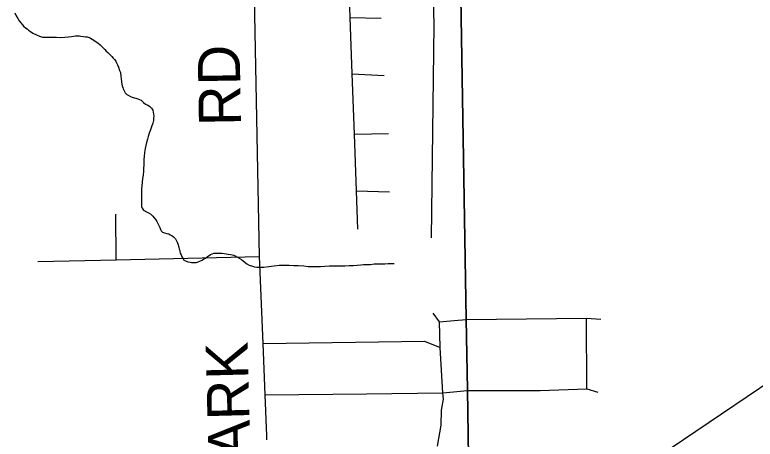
# Model space of a CAD drawing. Extents: x -59 to 82, y -3 to 49.
# Drawn here: x -51.187 to -50.187, y 46.792 to 47.366 of the extents above; entities that cross this region are included whole.
import ezdxf

# ---------------------------------------------------------------- set-up
doc = ezdxf.new("R2010")
doc.units = 0
for name, color, linetype in [('GM_X_Corporation', 7, 'Continuous'), ('GM_X_County_Road', 7, 'Continuous'), ('GM_X_County_Road_Text', 7, 'Continuous'), ('GM_X_Minor_River', 7, 'Continuous'), ('GM_X_Rail_Line', 7, 'Continuous'), ('GM_X_Township_Road', 7, 'Continuous')]:
    doc.layers.add(name, color=color, linetype=linetype)

msp = doc.modelspace()

# ---------------------------------------------------------------- linework, layer by layer
at = {"layer": 'GM_X_Corporation'}
for p, q in [((-50.5771, 46.9545), (-50.5847, 47.4155)), ((-50.5847, 47.4155), (-50.5771, 46.9545)), ((-50.5755, 46.8588), (-50.5771, 46.9545)), ((-50.5771, 46.9545), (-50.5755, 46.8588)), ((-50.5728, 46.6943), (-50.5755, 46.8588)), ((-50.5755, 46.8588), (-50.5728, 46.6943))]:
    msp.add_line(p, q, dxfattribs=at)
at = {"layer": 'GM_X_County_Road'}
for p, q in [((-50.8566, 47.039), (-50.8648, 47.4723)), ((-50.8518, 46.9215), (-50.8566, 47.039)), ((-50.8489, 46.8521), (-50.8518, 46.9215)), ((-50.8467, 46.7967), (-50.8489, 46.8521)), ((-50.8466, 46.7913), (-50.8467, 46.7967))]:
    msp.add_line(p, q, dxfattribs=at)
at = {"layer": 'GM_X_Minor_River'}
for p, q in [((-51.1872, 47.3684), (-51.1853, 47.3642)), ((-51.1853, 47.3642), (-51.183, 47.3605)), ((-51.183, 47.3605), (-51.1814, 47.3574)), ((-51.1814, 47.3574), (-51.1791, 47.3548)), ((-51.1791, 47.3548), (-51.1768, 47.3521)), ((-51.1768, 47.3521), (-51.1749, 47.3499)), ((-51.1749, 47.3499), (-51.173, 47.348)), ((-51.173, 47.348), (-51.1707, 47.3469)), ((-51.1707, 47.3469), (-51.1688, 47.345)), ((-51.1688, 47.345), (-51.1661, 47.3431)), ((-51.1661, 47.3431), (-51.1627, 47.3408)), ((-51.1627, 47.3408), (-51.1581, 47.3386)), ((-51.1581, 47.3386), (-51.1539, 47.3367)), ((-51.1539, 47.3367), (-51.1497, 47.3356)), ((-51.1106, 47.3363), (-51.108, 47.3367)), ((-51.108, 47.3367), (-51.105, 47.3371)), ((-51.105, 47.3371), (-51.1027, 47.3371)), ((-51.1027, 47.3371), (-51.1, 47.3371)), ((-51.1, 47.3371), (-51.0981, 47.3367)), ((-51.0981, 47.3367), (-51.0943, 47.3364)), ((-51.1497, 47.3356), (-51.1467, 47.3356)), ((-51.1467, 47.3356), (-51.1437, 47.3353)), ((-51.1437, 47.3353), (-51.1403, 47.3353)), ((-51.1403, 47.3353), (-51.1361, 47.3353)), ((-51.1361, 47.3353), (-51.1308, 47.3354)), ((-51.1308, 47.3354), (-51.1251, 47.335)), ((-51.1251, 47.335), (-51.1197, 47.3354)), ((-51.1197, 47.3354), (-51.1148, 47.3359)), ((-51.1148, 47.3359), (-51.1106, 47.3363)), ((-51.0943, 47.3364), (-51.0917, 47.336)), ((-51.0917, 47.336), (-51.0894, 47.3357)), ((-51.0894, 47.3357), (-51.0867, 47.3349)), ((-51.0867, 47.3349), (-51.0848, 47.3342)), ((-51.0848, 47.3342), (-51.0825, 47.3327)), ((-51.0825, 47.3327), (-51.0749, 47.3278)), ((-51.0749, 47.3278), (-51.0718, 47.3251)), ((-51.0718, 47.3251), (-51.0688, 47.3221)), ((-51.0688, 47.3221), (-51.0657, 47.3187)), ((-51.0657, 47.3187), (-51.0638, 47.3164)), ((-51.0638, 47.3164), (-51.0615, 47.3146)), ((-51.0615, 47.3146), (-51.0592, 47.3123)), ((-51.0592, 47.3123), (-51.0561, 47.3093)), ((-51.0561, 47.3093), (-51.0542, 47.307)), ((-51.0542, 47.307), (-51.0523, 47.3051)), ((-51.0523, 47.3051), (-51.0508, 47.3029)), ((-51.0508, 47.3029), (-51.0496, 47.3006)), ((-51.0496, 47.3006), (-51.0484, 47.2979)), ((-51.0484, 47.2979), (-51.0473, 47.2949)), ((-51.0473, 47.2949), (-51.0457, 47.2904)), ((-51.0457, 47.2904), (-51.0442, 47.2877)), ((-51.0442, 47.2877), (-51.0438, 47.2828)), ((-51.0438, 47.2828), (-51.0433, 47.279)), ((-51.0433, 47.279), (-51.0429, 47.2752)), ((-51.0429, 47.2752), (-51.0425, 47.2721)), ((-51.0425, 47.2721), (-51.0421, 47.2695)), ((-51.0421, 47.2695), (-51.0413, 47.2676)), ((-51.0413, 47.2676), (-51.041, 47.2657)), ((-51.041, 47.2657), (-51.0394, 47.263)), ((-51.0394, 47.263), (-51.0379, 47.2604)), ((-51.0379, 47.2604), (-51.036, 47.2581)), ((-51.036, 47.2581), (-51.034, 47.257)), ((-51.034, 47.257), (-51.031, 47.2551)), ((-51.031, 47.2551), (-51.0287, 47.2544)), ((-51.0287, 47.2544), (-51.026, 47.2536)), ((-51.026, 47.2536), (-51.0238, 47.2529)), ((-51.0238, 47.2529), (-51.0211, 47.2521)), ((-51.0211, 47.2521), (-51.0188, 47.2514)), ((-51.0188, 47.2514), (-51.0165, 47.2503)), ((-51.0165, 47.2503), (-51.0131, 47.2473)), ((-51.0131, 47.2473), (-51.0104, 47.245)), ((-51.0104, 47.245), (-51.0074, 47.2435)), ((-51.0074, 47.2435), (-51.0051, 47.2424)), ((-51.0051, 47.2424), (-51.0024, 47.2394)), ((-51.0024, 47.2394), (-51.0008, 47.2367)), ((-51.0008, 47.2367), (-50.9993, 47.2287)), ((-50.9993, 47.2287), (-50.9996, 47.2261)), ((-51.0007, 47.2192), (-51.0026, 47.2143)), ((-51, 47.223), (-51.0007, 47.2192)), ((-50.9996, 47.2261), (-51, 47.223)), ((-51.004, 47.2101), (-51.0055, 47.2059)), ((-51.0026, 47.2143), (-51.004, 47.2101)), ((-51.0081, 47.1975), (-51.0092, 47.1933)), ((-51.007, 47.2013), (-51.0081, 47.1975)), ((-51.0055, 47.2059), (-51.007, 47.2013)), ((-51.0103, 47.1891), (-51.0111, 47.185)), ((-51.0092, 47.1933), (-51.0103, 47.1891)), ((-51.0118, 47.1796), (-51.0125, 47.1743)), ((-51.0111, 47.185), (-51.0118, 47.1796)), ((-51.0125, 47.1743), (-51.0128, 47.1701)), ((-51.0128, 47.1701), (-51.0128, 47.1659)), ((-51.0128, 47.1621), (-51.0131, 47.1587)), ((-51.0131, 47.1587), (-51.0131, 47.1542)), ((-51.0128, 47.1659), (-51.0128, 47.1621)), ((-51.0138, 47.1492), (-51.0145, 47.1443)), ((-51.0131, 47.1542), (-51.0138, 47.1492)), ((-51.0149, 47.1397), (-51.0156, 47.1348)), ((-51.0145, 47.1443), (-51.0149, 47.1397)), ((-51.0156, 47.1348), (-51.0159, 47.1306)), ((-51.0159, 47.1306), (-51.0159, 47.1275)), ((-51.0159, 47.1275), (-51.0159, 47.1245)), ((-51.0159, 47.1245), (-51.0162, 47.1215)), ((-51.0162, 47.1215), (-51.0162, 47.1192)), ((-51.0162, 47.1192), (-51.0162, 47.1158)), ((-51.0162, 47.1158), (-51.0162, 47.1131)), ((-51.0162, 47.1131), (-51.0162, 47.1112)), ((-51.0162, 47.1112), (-51.0161, 47.1089)), ((-51.0161, 47.1089), (-51.0161, 47.1066)), ((-51.0161, 47.1066), (-51.0153, 47.1044)), ((-51.0153, 47.1044), (-51.0134, 47.1017)), ((-51.0134, 47.1017), (-51.0092, 47.0995)), ((-51.0092, 47.0995), (-51.0066, 47.098)), ((-51.0066, 47.098), (-51.0035, 47.0965)), ((-51.0035, 47.0965), (-51.0008, 47.0938)), ((-51.0008, 47.0938), (-50.9989, 47.0912)), ((-50.9989, 47.0912), (-50.9966, 47.0885)), ((-50.9966, 47.0885), (-50.9951, 47.0866)), ((-50.9951, 47.0866), (-50.9912, 47.0783)), ((-50.9912, 47.0783), (-50.9904, 47.0756)), ((-50.9904, 47.0756), (-50.9896, 47.0738)), ((-50.9896, 47.0738), (-50.9877, 47.0722)), ((-50.9877, 47.0722), (-50.9851, 47.0711)), ((-50.9851, 47.0711), (-50.982, 47.07)), ((-50.982, 47.07), (-50.979, 47.0696)), ((-50.979, 47.0696), (-50.9771, 47.0685)), ((-50.9771, 47.0685), (-50.9752, 47.0674)), ((-50.9752, 47.0674), (-50.9729, 47.0659)), ((-50.9729, 47.0659), (-50.9702, 47.0629)), ((-50.9702, 47.0629), (-50.969, 47.061)), ((-50.969, 47.061), (-50.9679, 47.0587)), ((-50.9679, 47.0587), (-50.9667, 47.0561)), ((-50.9667, 47.0561), (-50.9655, 47.0519)), ((-50.9655, 47.0519), (-50.9651, 47.0492)), ((-50.9651, 47.0492), (-50.9644, 47.0473)), ((-50.9644, 47.0473), (-50.964, 47.0454)), ((-50.964, 47.0454), (-50.9636, 47.0435)), ((-50.9636, 47.0435), (-50.9624, 47.0413)), ((-50.9624, 47.0413), (-50.9616, 47.0386)), ((-50.9616, 47.0386), (-50.9601, 47.0367)), ((-50.9601, 47.0367), (-50.9586, 47.0344)), ((-50.9316, 47.0358), (-50.9293, 47.0369)), ((-50.9293, 47.0369), (-50.9267, 47.0392)), ((-50.9267, 47.0392), (-50.9244, 47.0404)), ((-50.9244, 47.0404), (-50.9226, 47.0419)), ((-50.9226, 47.0419), (-50.9207, 47.0427)), ((-50.9207, 47.0427), (-50.9184, 47.0435)), ((-50.9184, 47.0435), (-50.9161, 47.0435)), ((-50.9161, 47.0435), (-50.9074, 47.0435)), ((-50.9074, 47.0435), (-50.9043, 47.0432)), ((-50.9043, 47.0432), (-50.9017, 47.0428)), ((-50.9017, 47.0428), (-50.899, 47.0421)), ((-50.899, 47.0421), (-50.8956, 47.0417)), ((-50.8956, 47.0417), (-50.8933, 47.0414)), ((-50.8933, 47.0414), (-50.8914, 47.041)), ((-50.8914, 47.041), (-50.8895, 47.0399)), ((-50.8895, 47.0399), (-50.8872, 47.0387)), ((-50.8872, 47.0387), (-50.8842, 47.0369)), ((-50.8842, 47.0369), (-50.8811, 47.035)), ((-50.9586, 47.0344), (-50.9567, 47.0333)), ((-50.9567, 47.0333), (-50.9536, 47.0318)), ((-50.9536, 47.0318), (-50.9502, 47.0315)), ((-50.9502, 47.0315), (-50.9483, 47.0311)), ((-50.9483, 47.0311), (-50.9464, 47.0311)), ((-50.9464, 47.0311), (-50.9445, 47.0311)), ((-50.9445, 47.0311), (-50.9422, 47.0311)), ((-50.9422, 47.0311), (-50.9403, 47.0315)), ((-50.9403, 47.0315), (-50.9365, 47.0331)), ((-50.9365, 47.0331), (-50.9339, 47.0342)), ((-50.9339, 47.0342), (-50.9316, 47.0358)), ((-50.8811, 47.035), (-50.8788, 47.0331)), ((-50.8788, 47.0331), (-50.8761, 47.0312)), ((-50.8761, 47.0312), (-50.8735, 47.0293)), ((-50.8735, 47.0293), (-50.8704, 47.0274)), ((-50.8704, 47.0274), (-50.8662, 47.026)), ((-50.8438, 47.0257), (-50.8366, 47.0265)), ((-50.8366, 47.0265), (-50.8298, 47.0273)), ((-50.8298, 47.0273), (-50.8229, 47.0274)), ((-50.8229, 47.0274), (-50.8165, 47.0274)), ((-50.8165, 47.0274), (-50.81, 47.0271)), ((-50.81, 47.0271), (-50.8043, 47.0268)), ((-50.8043, 47.0268), (-50.7967, 47.0264)), ((-50.7967, 47.0264), (-50.791, 47.0257)), ((-50.7682, 47.0259), (-50.7618, 47.0263)), ((-50.7618, 47.0263), (-50.7561, 47.0263)), ((-50.7561, 47.0263), (-50.7508, 47.0267)), ((-50.7508, 47.0267), (-50.7458, 47.0264)), ((-50.7458, 47.0264), (-50.7413, 47.0264)), ((-50.7413, 47.0264), (-50.7352, 47.0268)), ((-50.7352, 47.0268), (-50.7299, 47.0269)), ((-50.7299, 47.0269), (-50.7246, 47.0273)), ((-50.7246, 47.0273), (-50.7197, 47.0277)), ((-50.7197, 47.0277), (-50.7159, 47.0281)), ((-50.7159, 47.0281), (-50.7113, 47.0281)), ((-50.7113, 47.0281), (-50.7064, 47.0285)), ((-50.7064, 47.0285), (-50.7018, 47.029)), ((-50.7018, 47.029), (-50.6969, 47.0294)), ((-50.6969, 47.0294), (-50.6923, 47.0294)), ((-50.6923, 47.0294), (-50.687, 47.0294)), ((-50.687, 47.0294), (-50.6825, 47.0295)), ((-50.6825, 47.0295), (-50.6744, 47.0298)), ((-50.8662, 47.026), (-50.8632, 47.0252)), ((-50.8632, 47.0252), (-50.8601, 47.0245)), ((-50.8601, 47.0245), (-50.8563, 47.0245)), ((-50.8563, 47.0245), (-50.8506, 47.0249)), ((-50.8506, 47.0249), (-50.8438, 47.0257)), ((-50.791, 47.0257), (-50.785, 47.0254)), ((-50.785, 47.0254), (-50.7793, 47.0254)), ((-50.7793, 47.0254), (-50.7743, 47.0254)), ((-50.7743, 47.0254), (-50.7682, 47.0259))]:
    msp.add_line(p, q, dxfattribs=at)
at = {"layer": 'GM_X_Rail_Line'}
for p, q in [((-50.2324, 46.8266), (-50.0635, 46.9408)), ((-50.345, 46.7507), (-50.2324, 46.8266))]:
    msp.add_line(p, q, dxfattribs=at)
at = {"layer": 'GM_X_Township_Road'}
for p, q in [((-50.7339, 47.362), (-50.7363, 47.4292)), ((-50.6206, 47.3516), (-50.6221, 47.4154)), ((-50.7339, 47.362), (-50.692, 47.3613)), ((-50.7312, 47.2858), (-50.7339, 47.362)), ((-50.6242, 47.0642), (-50.6206, 47.3516)), ((-50.7312, 47.2858), (-50.6879, 47.2836)), ((-50.7283, 47.2043), (-50.7312, 47.2858)), ((-50.7283, 47.2043), (-50.6822, 47.2052)), ((-50.7256, 47.1277), (-50.7283, 47.2043)), ((-50.7256, 47.1277), (-50.6807, 47.1263)), ((-50.7238, 47.0759), (-50.7256, 47.1277)), ((-51.0504, 47.0348), (-51.0505, 47.0963)), ((-51.0504, 47.0348), (-50.8566, 47.039)), ((-51.1563, 47.0325), (-51.0504, 47.0348)), ((-50.6135, 46.9508), (-50.6218, 46.9624)), ((-50.6135, 46.9508), (-50.5937, 46.9525)), ((-50.6124, 46.9164), (-50.6135, 46.9508)), ((-50.5937, 46.9525), (-50.5769, 46.954)), ((-50.5769, 46.954), (-50.4146, 46.9559)), ((-50.4142, 46.8602), (-50.4146, 46.9559)), ((-50.4146, 46.9559), (-50.3951, 46.9544)), ((-50.8518, 46.9215), (-50.6334, 46.9247)), ((-50.6334, 46.9247), (-50.6124, 46.9164)), ((-50.609, 46.8549), (-50.6124, 46.9164)), ((-50.609, 46.8549), (-50.5753, 46.8583)), ((-50.5753, 46.8583), (-50.5548, 46.8583)), ((-50.5548, 46.8583), (-50.4771, 46.8582)), ((-50.4771, 46.8582), (-50.4142, 46.8602)), ((-50.4142, 46.8602), (-50.3994, 46.856)), ((-50.8489, 46.8521), (-50.7119, 46.8536)), ((-50.7119, 46.8536), (-50.609, 46.8549)), ((-50.6105, 46.8314), (-50.608, 46.8462)), ((-50.608, 46.8462), (-50.609, 46.8549)), ((-50.6109, 46.8114), (-50.6105, 46.8314)), ((-50.6158, 46.783), (-50.6109, 46.8114))]:
    msp.add_line(p, q, dxfattribs=at)

# ---------------------------------------------------------------- texts
at = {"layer": 'GM_X_County_Road_Text'}
for s, rotation, p in [('RD', 90.9891, (-50.8815, 47.2159)), ('PARK', 91.5139, (-50.8673, 46.7174))]:
    msp.add_text(s, height=0.05682, rotation=rotation, dxfattribs=at).set_placement(p)

doc.saveas('drawing.dxf')
